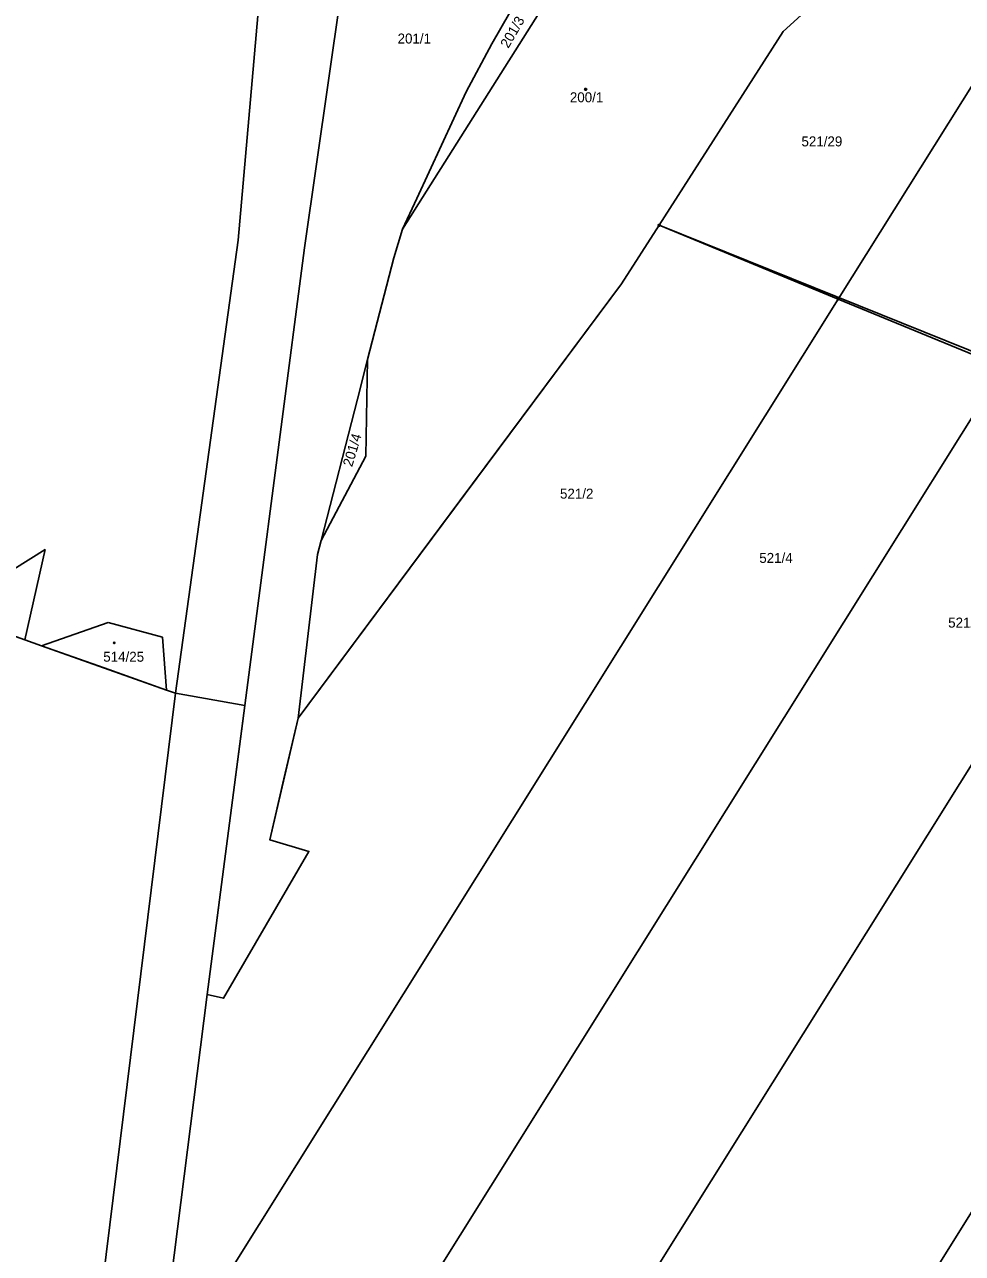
# Model space of a CAD drawing. Extents: x -634640 to -629202, y -1196156 to -1190068.
# Drawn here: x -631649.3 to -631489.7, y -1193075.2 to -1192866.1 of the extents above; entities that cross this region are included whole.
import ezdxf

# ---------------------------------------------------------------- set-up
doc = ezdxf.new("R2010")
doc.units = 0
for name, color, linetype in [('Obvod šetřený', 7, 'Continuous'), ('Vrstva 1', 7, 'Continuous'), ('Vrstva 2', 7, 'Continuous'), ('Vrstva 3', 7, 'Continuous'), ('Vrstva 8', 7, 'Continuous')]:
    doc.layers.add(name, color=color, linetype=linetype)

msp = doc.modelspace()

# ---------------------------------------------------------------- linework, layer by layer
at = {"layer": 'Obvod šetřený'}
for points in [[(-631618.25, -1193031.14), (-631611.834, -1192981.924), (-631623.66, -1192979.87), (-631625.15, -1192979.34), (-631635.795, -1192975.56), (-631646.44, -1192971.78), (-631649.28, -1192970.78), (-631655.33, -1192968.63), (-631661.38, -1192966.48), (-631662.38, -1192965.83), (-631668.24, -1192962), (-631674.1, -1192958.17), (-631680.105, -1192954.245), (-631686.11, -1192950.32), (-631684.345, -1192947.36), (-631682.58, -1192944.4), (-631672.41, -1192927.33), (-631687.02, -1192918.675), (-631701.63, -1192910.02), (-631706.39, -1192907.2), (-631712.01, -1192894.91), (-631721.66, -1192873.8)], [(-631453.34, -1192936.49), (-631468.02, -1192930.43), (-631482.7, -1192924.37), (-631510.81, -1192912.78), (-631526.055, -1192906.495), (-631541.3, -1192900.21), (-631547.7, -1192910.19), (-631575.23, -1192947.14), (-631602.76, -1192984.09)], [(-631541.3, -1192900.21), (-631383.293, -1192963.849), (-631351.65, -1192913.33)], [(-631602.76, -1192984.09), (-631605.175, -1192994.44), (-631607.59, -1193004.79), (-631600.94, -1193006.78), (-631608.2, -1193019.275), (-631615.46, -1193031.77), (-631618.25, -1193031.14)]]:
    msp.add_lwpolyline(points, dxfattribs=at)
at = {"layer": 'Vrstva 1'}
for p, q in [((-631612.95, -1192902.74), (-631608.14, -1192847.29)), ((-631593.6, -1192847.88), (-631601.68, -1192904.03)), ((-631584.97, -1192900.87), (-631560.39, -1192861.89)), ((-631564.65, -1192860.37), (-631569.79, -1192869.32)), ((-631520.17, -1192867.23), (-631515.85, -1192863.31)), ((-631520.17, -1192867.23), (-631541.3, -1192900.21)), ((-631481.95, -1192866.69), (-631510.81, -1192912.78)), ((-631569.79, -1192869.32), (-631574.13, -1192877.52)), ((-631574.13, -1192877.52), (-631582.55, -1192895.64)), ((-631582.55, -1192895.64), (-631584.97, -1192900.87)), ((-631586.46, -1192905.77), (-631584.97, -1192900.87)), ((-631541.3, -1192900.21), (-631547.7, -1192910.19)), ((-631541.3, -1192900.21), (-631510.81, -1192912.78)), ((-631623.66, -1192979.87), (-631612.95, -1192902.74)), ((-631618.25, -1193031.14), (-631601.68, -1192904.03)), ((-631586.46, -1192905.77), (-631590.94, -1192923.07)), ((-631385.28, -1192903.9), (-631512.56, -1193107.16)), ((-631602.76, -1192984.09), (-631547.7, -1192910.19)), ((-631510.81, -1192912.78), (-631623.19, -1193092.24)), ((-631590.94, -1192923.07), (-631592.68, -1192929.81)), ((-631482.7, -1192924.37), (-631591.76, -1193098.54)), ((-631590.94, -1192923.07), (-631591.23, -1192939.52)), ((-631598.85, -1192953.87), (-631592.68, -1192929.81)), ((-631453.34, -1192936.49), (-631557.17, -1193102.3)), ((-631591.23, -1192939.52), (-631598.85, -1192953.87)), ((-631599.46, -1192956.26), (-631598.85, -1192953.87)), ((-631645.86, -1192955.37), (-631662.38, -1192965.83)), ((-631649.28, -1192970.78), (-631645.86, -1192955.37)), ((-631602.76, -1192984.09), (-631599.46, -1192956.26)), ((-631649.28, -1192970.78), (-631661.38, -1192966.48)), ((-631635.11, -1192967.8), (-631646.44, -1192971.78)), ((-631625.85, -1192970.34), (-631635.11, -1192967.8)), ((-631625.15, -1192979.34), (-631625.85, -1192970.34)), ((-631646.44, -1192971.78), (-631649.28, -1192970.78)), ((-631625.15, -1192979.34), (-631646.44, -1192971.78)), ((-631636.76, -1193085.85), (-631623.66, -1192979.87)), ((-631623.66, -1192979.87), (-631625.15, -1192979.34)), ((-631602.76, -1192984.09), (-631607.59, -1193004.79)), ((-631600.94, -1193006.78), (-631607.59, -1193004.79)), ((-631615.46, -1193031.77), (-631600.94, -1193006.78)), ((-631625.57, -1193089.03), (-631618.25, -1193031.14)), ((-631618.25, -1193031.14), (-631615.46, -1193031.77))]:
    msp.add_line(p, q, dxfattribs=at)
at = {"layer": 'Vrstva 3'}
for points in [[(-631553.72, -1192876.93), (-631553.63, -1192877.08), (-631553.72, -1192877.23), (-631553.9, -1192877.23), (-631553.99, -1192877.08), (-631553.9, -1192876.93), (-631553.72, -1192876.93)], [(-631634.01, -1192971.19), (-631633.949, -1192971.29), (-631634.01, -1192971.39), (-631634.13, -1192971.39), (-631634.191, -1192971.29), (-631634.13, -1192971.19), (-631634.01, -1192971.19)]]:
    msp.add_lwpolyline(points, dxfattribs=at)
at = {"layer": 'Vrstva 8'}
for points in [[(-631541.21, -1192900.06), (-631541.12, -1192900.21), (-631541.21, -1192900.36), (-631541.39, -1192900.36), (-631541.48, -1192900.21), (-631541.39, -1192900.06), (-631541.21, -1192900.06)], [(-631510.72, -1192912.63), (-631510.63, -1192912.78), (-631510.72, -1192912.93), (-631510.9, -1192912.93), (-631510.99, -1192912.78), (-631510.9, -1192912.63), (-631510.72, -1192912.63)]]:
    msp.add_lwpolyline(points, dxfattribs=at)

# ---------------------------------------------------------------- texts
at = {"layer": 'Vrstva 2'}
for s, rotation, p in [('201/3', 59.93139, (-631566.981, -1192870.205)), ('201/4', 73.2813, (-631593.572, -1192941.423))]:
    msp.add_text(s, height=1.7, rotation=rotation, dxfattribs=at).set_placement(p)
for s, p in [('201/1', (-631585.833, -1192869.28)), ('200/1', (-631556.503, -1192879.28)), ('521/29', (-631517.07, -1192886.79)), ('521/2', (-631558.183, -1192946.74)), ('521/4', (-631524.253, -1192957.68)), ('521/5', (-631492.093, -1192968.69)), ('514/25', (-631635.943, -1192974.5))]:
    msp.add_text(s, height=1.7, dxfattribs=at).set_placement(p)

doc.saveas('drawing.dxf')
